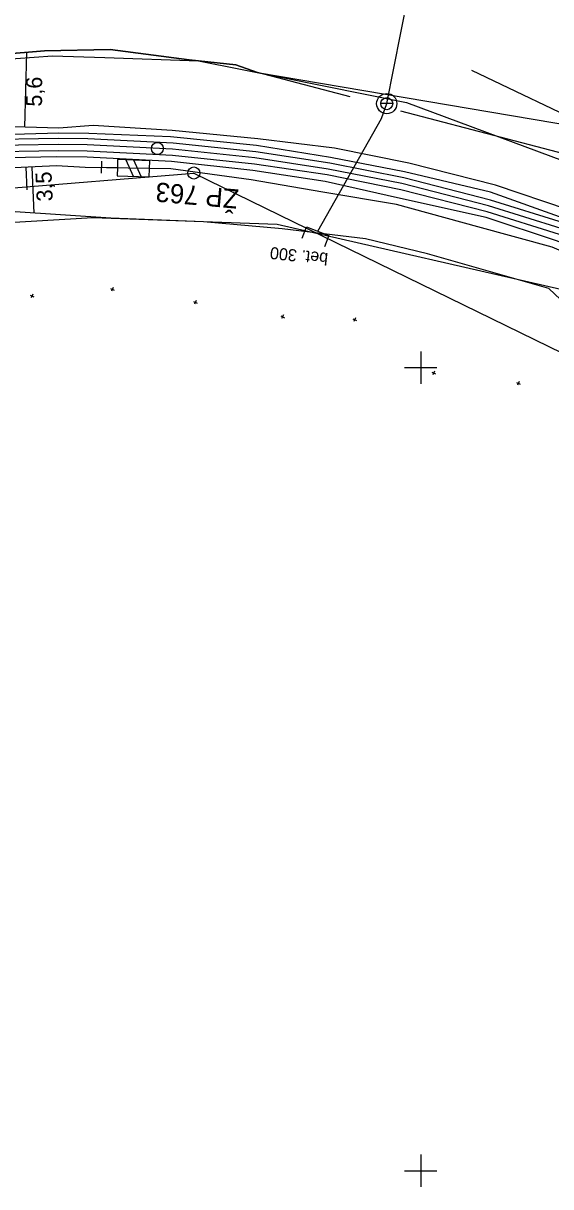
# Model space of a CAD drawing. Extents: x -805011 to -803920, y -1150790 to -1150234.
# Drawn here: x -804349.5 to -804283.8, y -1150602 to -1150457.1 of the extents above; entities that cross this region are included whole.
import ezdxf

# ---------------------------------------------------------------- set-up
doc = ezdxf.new("R2010")
doc.units = 0
for name, color, linetype in [('0381KM032-037P - Vrstva 1', 7, 'Continuous'), ('0381KM032-037P - Vrstva 17', 7, 'Continuous'), ('0381KM032-037P - Vrstva 19', 7, 'Continuous'), ('0381KM032-037P - Vrstva 4', 7, 'Continuous'), ('0381KM032-037P - Vrstva 41', 7, 'Continuous'), ('0381KM032-037P - Vrstva 43', 7, 'Continuous'), ('0381KM032-037P - Vrstva 48', 7, 'Continuous'), ('0381KM032-037P - Vrstva 49', 7, 'Continuous'), ('0381KM032-037P - Vrstva 51', 7, 'Continuous'), ('0381KM032-037P - Vrstva 7', 7, 'Continuous'), ('hran DP - hran DP', 7, 'Continuous'), ('krizky_1000 - Vrstva 1', 7, 'Continuous'), ('vyt_sit - polygon', 7, 'Continuous'), ('vyt_sit - stávající', 7, 'Continuous')]:
    doc.layers.add(name, color=color, linetype=linetype)

msp = doc.modelspace()

# ---------------------------------------------------------------- linework, layer by layer
at = {"layer": '0381KM032-037P - Vrstva 1'}
for points in [[(-804345.19, -1150472.22), (-804355.1, -1150472.39), (-804364.37, -1150472.93), (-804373.68, -1150473.77), (-804382.25, -1150474.73), (-804390.38, -1150475.71), (-804394.38, -1150476.22)], [(-804222.98, -1150515.09), (-804226.42, -1150512.48), (-804234.26, -1150506.83), (-804242.54, -1150501.49), (-804250.96, -1150496.61), (-804260.8, -1150491.55), (-804271.59, -1150486.76), (-804282.48, -1150482.69), (-804291.53, -1150479.85), (-804302.34, -1150477.08), (-804311.51, -1150475.27), (-804320.67, -1150473.88), (-804330.92, -1150472.81), (-804341.55, -1150472.27), (-804345.19, -1150472.22)]]:
    msp.add_lwpolyline(points, dxfattribs=at)
at = {"layer": '0381KM032-037P - Vrstva 17'}
msp.add_line((-804323.06, -1150462.29), (-804328.85, -1150461.67), dxfattribs=at)
for points in [[(-804328.85, -1150461.67), (-804338.71, -1150460.38), (-804346.87, -1150460.56), (-804368.54, -1150462.33)], [(-804308.78, -1150466.29), (-804320.34, -1150463.27), (-804323.06, -1150462.29)], [(-804223.8, -1150504.14), (-804238.39, -1150493.96), (-804260.56, -1150483.05), (-804280.24, -1150473.89), (-804302.47, -1150468.07)]]:
    msp.add_lwpolyline(points, dxfattribs=at)
at = {"layer": '0381KM032-037P - Vrstva 19'}
msp.add_line((-804304.23, -1150467.13), (-804292.59, -1150408.12), dxfattribs=at)
msp.add_lwpolyline([(-804312.83, -1150483), (-804304.87, -1150468.97), (-804304.23, -1150467.13)], dxfattribs=at)
at = {"layer": '0381KM032-037P - Vrstva 4'}
for points in [[(-804225.7, -1150511.47), (-804233.93, -1150505.38), (-804241.84, -1150500.35), (-804251.18, -1150495.03), (-804260.27, -1150490.25), (-804271.39, -1150485.02), (-804282.1, -1150481.42), (-804291.28, -1150478.15), (-804302, -1150475.62), (-804311.22, -1150473.82), (-804320.47, -1150472.35), (-804331.17, -1150471.28), (-804341.36, -1150470.84), (-804345.11, -1150470.79), (-804355.15, -1150471.09), (-804364.49, -1150471.64), (-804373.72, -1150472.46), (-804382.56, -1150473.46), (-804390.64, -1150474.3), (-804394.58, -1150474.82), (-804430.68, -1150479.4), (-804471.16, -1150484.87), (-804515.79, -1150490.21)], [(-804222.47, -1150514.31), (-804225.93, -1150511.88), (-804233.81, -1150506.22), (-804242.12, -1150500.85), (-804250.57, -1150495.96), (-804260.44, -1150490.89), (-804271.28, -1150486.07), (-804282.21, -1150481.99), (-804291.28, -1150479.14), (-804302.11, -1150476.36), (-804311.33, -1150474.54), (-804320.55, -1150473.14), (-804330.83, -1150472.06), (-804341.5, -1150471.52), (-804345.16, -1150471.47), (-804355.1, -1150471.64), (-804364.39, -1150472.17), (-804373.73, -1150473.02), (-804382.33, -1150473.97), (-804390.45, -1150474.97), (-804394.45, -1150475.48), (-804430.79, -1150480.07), (-804470.48, -1150485.06), (-804515.61, -1150490.8)], [(-804223.37, -1150515.97), (-804226.85, -1150513.1), (-804234.67, -1150507.48), (-804242.93, -1150502.16), (-804251.31, -1150497.29), (-804261.13, -1150492.25), (-804271.85, -1150487.49), (-804282.71, -1150483.42), (-804291.73, -1150480.59), (-804302.46, -1150477.85), (-804311.66, -1150476.01), (-804320.71, -1150474.65), (-804330.94, -1150473.58), (-804341.55, -1150473.05), (-804345.16, -1150472.99), (-804355.02, -1150473.16), (-804364.28, -1150473.69), (-804373.57, -1150474.51), (-804382.12, -1150475.46), (-804390.26, -1150476.46), (-804394.25, -1150476.96), (-804430.61, -1150481.56), (-804470.33, -1150486.56), (-804515.43, -1150492.3)], [(-804235.83, -1150507.71), (-804243.11, -1150502.63), (-804252.43, -1150497.68), (-804261.4, -1150493.06), (-804272.11, -1150488.47), (-804283.06, -1150484.22), (-804291.82, -1150481.32), (-804302.89, -1150478.85), (-804311.92, -1150476.81), (-804320.92, -1150475.47), (-804331.06, -1150474.34), (-804341.56, -1150473.81), (-804345.45, -1150473.75), (-804355.04, -1150473.96), (-804364.32, -1150474.45), (-804373.64, -1150475.34), (-804382.1, -1150476.35), (-804390.24, -1150477.29), (-804394.24, -1150477.85), (-804430.45, -1150482.3), (-804470.19, -1150487.36), (-804515.37, -1150493.06)]]:
    msp.add_lwpolyline(points, dxfattribs=at)
at = {"layer": '0381KM032-037P - Vrstva 41'}
msp.add_line((-804303.48, -1150467.13), (-804304.98, -1150467.13), dxfattribs=at)
for radius in [1.26, 0.75]:
    msp.add_circle((-804304.23, -1150467.13), radius, dxfattribs=at)
at = {"layer": '0381KM032-037P - Vrstva 43'}
msp.add_lwpolyline([(-804314.77, -1150483.86), (-804314.23, -1150482.46), (-804311.43, -1150483.54), (-804311.97, -1150484.94)], dxfattribs=at)
at = {"layer": '0381KM032-037P - Vrstva 48'}
for p, q in [((-804349.36, -1150470.06), (-804349.08, -1150460.74)), ((-804349.23, -1150475.05), (-804349.1, -1150477.88)), ((-804348.48, -1150475.02), (-804348.21, -1150480.75))]:
    msp.add_line(p, q, dxfattribs=at)
at = {"layer": '0381KM032-037P - Vrstva 49'}
for p, q in [((-804348.35, -1150490.85), (-804348.57, -1150491.31)), ((-804338.66, -1150490.13), (-804338.2, -1150490.35)), ((-804338.32, -1150490.01), (-804338.54, -1150490.47)), ((-804348.69, -1150490.97), (-804348.23, -1150491.19)), ((-804328.31, -1150491.76), (-804327.85, -1150491.98)), ((-804327.97, -1150491.64), (-804328.19, -1150492.1)), ((-804317.45, -1150493.56), (-804316.99, -1150493.78)), ((-804317.11, -1150493.44), (-804317.33, -1150493.9)), ((-804308.46, -1150493.92), (-804308, -1150494.14)), ((-804308.12, -1150493.8), (-804308.34, -1150494.26)), ((-804298.6, -1150500.57), (-804298.14, -1150500.79)), ((-804298.26, -1150500.45), (-804298.48, -1150500.91)), ((-804288.05, -1150501.85), (-804287.59, -1150502.07)), ((-804287.71, -1150501.73), (-804287.93, -1150502.19))]:
    msp.add_line(p, q, dxfattribs=at)
for points in [[(-804541.81, -1150485.21), (-804536.33, -1150485.99), (-804530.6, -1150485.02), (-804524.61, -1150484.28), (-804503.76, -1150480.94), (-804473.97, -1150476), (-804446.96, -1150472.02), (-804437.24, -1150471.08), (-804431.75, -1150470.1), (-804429.72, -1150469.73), (-804427.08, -1150469.25), (-804388.45, -1150464.13), (-804374.42, -1150462.03), (-804368.54, -1150462.33), (-804346.87, -1150460.56), (-804338.71, -1150460.38), (-804328.85, -1150461.67), (-804323.06, -1150462.29), (-804320.34, -1150463.27)], [(-804328.85, -1150461.67), (-804323.06, -1150462.29), (-804320.34, -1150463.27)], [(-804320.34, -1150463.27), (-804278.12, -1150470.41)], [(-804221.1, -1150510.47), (-804225.19, -1150510.8), (-804233.52, -1150504.69), (-804241.09, -1150499.46), (-804250.66, -1150494.51), (-804260.04, -1150488.87), (-804271.07, -1150483.89), (-804281.58, -1150480.34), (-804290.68, -1150477.29), (-804301.47, -1150474.53), (-804310.76, -1150472.67), (-804320.3, -1150471.51), (-804330.99, -1150470.46), (-804340.83, -1150469.83), (-804345.1, -1150470.19), (-804354.95, -1150469.89)], [(-804226.97, -1150514.32), (-804233.94, -1150510.78), (-804236.52, -1150508.57), (-804243.93, -1150503.82), (-804252.72, -1150498.82), (-804262.25, -1150494.6), (-804273.33, -1150489.4), (-804283.59, -1150485.01), (-804292.89, -1150482.47), (-804303.02, -1150479.68), (-804312.2, -1150478.16), (-804321.12, -1150476.62), (-804331.14, -1150475.24), (-804341.8, -1150475.06), (-804345.41, -1150474.87), (-804355.14, -1150475.34), (-804364.22, -1150475.73), (-804373.58, -1150476.33), (-804382.14, -1150477.38), (-804390.01, -1150478.23), (-804394.36, -1150478.78), (-804430.35, -1150482.91), (-804470.16, -1150488.05), (-804515.21, -1150493.93)], [(-804276.15, -1150497.56), (-804284.03, -1150490.16), (-804299.15, -1150485.83), (-804306.89, -1150483.98), (-804317.28, -1150482.7), (-804327.05, -1150481.84), (-804338.6, -1150481.41), (-804350.55, -1150480.59), (-804360.54, -1150481.11), (-804374.96, -1150483.29), (-804385.39, -1150485.41), (-804391.71, -1150485.5), (-804430.73, -1150489.32), (-804470.3, -1150492.85), (-804514.17, -1150497.56)]]:
    msp.add_lwpolyline(points, dxfattribs=at)
at = {"layer": '0381KM032-037P - Vrstva 51'}
msp.add_lwpolyline([(-804222.47, -1150514.31), (-804222.23, -1150513.73), (-804221.1, -1150510.47), (-804220.62, -1150508.07), (-804220.01, -1150502.88), (-804222.18, -1150500.57), (-804227.38, -1150496.55), (-804235.69, -1150490.06), (-804246.55, -1150486.97), (-804255.48, -1150481.87), (-804266.7, -1150476.32), (-804278.12, -1150470.41), (-804293.62, -1150463)], dxfattribs=at)
at = {"layer": '0381KM032-037P - Vrstva 7'}
for p, q in [((-804339.77, -1150474.28), (-804339.83, -1150475.78)), ((-804336.77, -1150474.13), (-804335.84, -1150476.16)), ((-804334.84, -1150476.2), (-804335.77, -1150474.17))]:
    msp.add_line(p, q, dxfattribs=at)
msp.add_lwpolyline([(-804339.8, -1150475.03), (-804337.8, -1150475.1), (-804337.83, -1150476.1), (-804333.84, -1150476.23), (-804333.77, -1150474.23), (-804337.77, -1150474.1), (-804337.8, -1150475.1)], dxfattribs=at)
msp.add_circle((-804332.82, -1150472.71), 0.75, dxfattribs=at)
at = {"layer": 'hran DP - hran DP'}
for p, q in [((-804374.01, -1150463.14), (-804345.91, -1150461.18)), ((-804345.91, -1150461.18), (-804339.38, -1150461.4)), ((-804339.38, -1150461.4), (-804327.71, -1150461.78)), ((-804327.71, -1150461.78), (-804317.22, -1150463.88)), ((-804317.22, -1150463.88), (-804301.77, -1150466.98)), ((-804301.77, -1150466.98), (-804268.19, -1150479.5)), ((-804340.86, -1150481.33), (-804372.75, -1150483.24)), ((-804317.89, -1150482.17), (-804340.86, -1150481.33)), ((-804276.4, -1150491.69), (-804317.89, -1150482.17))]:
    msp.add_line(p, q, dxfattribs=at)
at = {"layer": 'krizky_1000 - Vrstva 1'}
for points in [[(-804300, -1150498), (-804300, -1150502)], [(-804302, -1150500), (-804298, -1150500)], [(-804300, -1150598), (-804300, -1150602)], [(-804302, -1150600), (-804298, -1150600)]]:
    msp.add_lwpolyline(points, dxfattribs=at)
at = {"layer": 'vyt_sit - polygon'}
for p, q in [((-804444.16, -1150485.23), (-804328.27, -1150475.77)), ((-804328.27, -1150475.77), (-804184.81, -1150545.81))]:
    msp.add_line(p, q, dxfattribs=at)
at = {"layer": 'vyt_sit - stávající'}
msp.add_line((-804328.32, -1150475.77), (-804328.22, -1150475.77), dxfattribs=at)
msp.add_circle((-804328.27, -1150475.77), 0.756, dxfattribs=at)

# ---------------------------------------------------------------- texts
at = {"layer": '0381KM032-037P - Vrstva 43'}
msp.add_text('bet. 300', height=1.5, rotation=173.8026, dxfattribs=at).set_placement((-804311.48, -1150485.74))
at = {"layer": '0381KM032-037P - Vrstva 48'}
for s, rotation, p in [('5,6', 89.6695, (-804347.2, -1150467.5)), ('3,5', 92.7655, (-804345.85, -1150479.26))]:
    msp.add_text(s, height=2, rotation=rotation, dxfattribs=at).set_placement(p)
at = {"layer": 'vyt_sit - stávající'}
msp.add_text('ŽP 763', height=2.4, rotation=175, dxfattribs=at).set_placement((-804322.61, -1150477.83))

doc.saveas('drawing.dxf')
